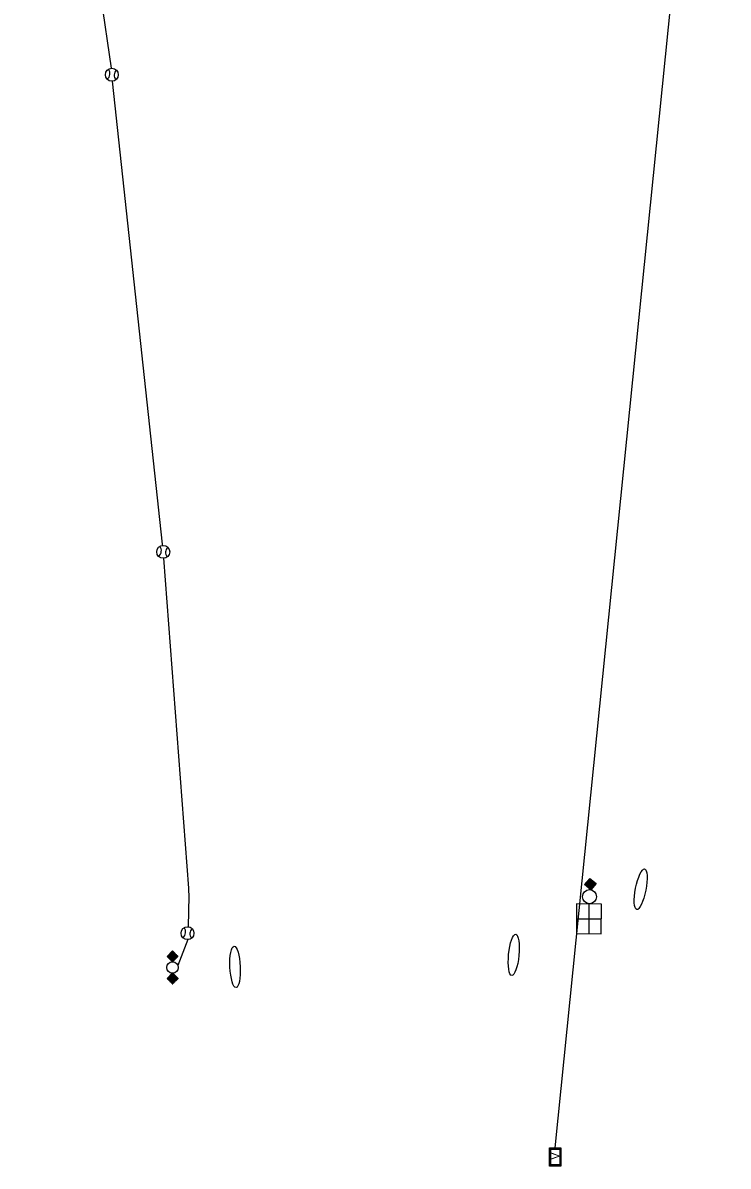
# Model space of a CAD drawing. Extents: x 584850 to 602551, y 145475 to 158627.
# Drawn here: x 594140 to 594577, y 153187 to 153895 of the extents above; entities that cross this region are included whole.
import ezdxf

# ---------------------------------------------------------------- set-up
doc = ezdxf.new("R2010")
doc.units = 0
doc.layers.add('B_MISC', color=7, linetype='Continuous')
doc.layers.add('E_RDWY', color=7, linetype='Continuous')

# ---------------------------------------------------------------- blocks, each defined once
blk = doc.blocks.new('PB24X42')
at = {"layer": 'E_RDWY'}
blk.add_circle((0, 0), 2, dxfattribs=at)
for centre, start, end in [((-2.59, 0.09), 308.3742, 47.6044), ((2.73, 0.07), 134.4184, 228.4474)]:
    blk.add_arc(centre, 2, start, end, dxfattribs=at)

msp = doc.modelspace()

# ---------------------------------------------------------------- linework, layer by layer
at = {"layer": 'B_MISC'}
for p, q in [((594469.73, 153198.28), (594576.82, 154259.36)), ((594194.8, 153867.11), (594139.91, 154245.19)), ((594226.44, 153572.23), (594195.44, 153859.06)), ((594242.7, 153359.11), (594227.19, 153563.53)), ((594242.51, 153335.26), (594242.84, 153354.47)), ((594242.02, 153327.29), (594235.82, 153311.35))]:
    msp.add_line(p, q, dxfattribs=at)
for centre, start, end in [((594176.91, 153565.37), 7.0373, 7.8773), ((594192.84, 153355.33), 359.01607, 4.33771)]:
    msp.add_arc(centre, 50, start, end, dxfattribs=at)
at = {"layer": 'E_RDWY'}
for p, q in [((594487.9, 153361.49), (594494.96, 153361.96)), ((594488.18, 153361.81), (594494.64, 153362.24)), ((594488.22, 153361.21), (594488.18, 153361.81)), ((594488.46, 153362.13), (594494.32, 153362.52)), ((594488.54, 153360.93), (594488.46, 153362.13)), ((594488.74, 153362.45), (594494, 153362.8)), ((594488.86, 153360.65), (594488.74, 153362.45)), ((594489.02, 153362.77), (594493.68, 153363.07)), ((594489.18, 153360.37), (594489.02, 153362.77)), ((594489.3, 153363.08), (594493.36, 153363.35)), ((594489.5, 153360.09), (594489.3, 153363.08)), ((594489.58, 153363.4), (594493.04, 153363.63)), ((594489.82, 153359.81), (594489.58, 153363.4)), ((594489.86, 153363.72), (594492.72, 153363.91)), ((594490.14, 153359.53), (594489.86, 153363.72)), ((594490.14, 153364.04), (594492.41, 153364.19)), ((594490.46, 153359.25), (594490.14, 153364.04)), ((594490.42, 153364.36), (594492.09, 153364.47)), ((594490.78, 153358.97), (594490.42, 153364.36)), ((594490.7, 153364.68), (594491.77, 153364.75)), ((594491.1, 153358.69), (594490.7, 153364.68)), ((594490.98, 153365), (594491.45, 153365.03)), ((594491.42, 153358.41), (594490.98, 153365)), ((594491.73, 153358.26), (594491.27, 153365.19)), ((594492.01, 153358.58), (594491.58, 153364.91)), ((594492.29, 153358.9), (594491.9, 153364.63)), ((594492.56, 153359.22), (594492.22, 153364.35)), ((594492.84, 153359.54), (594492.54, 153364.07)), ((594493.12, 153359.86), (594492.86, 153363.79)), ((594493.4, 153360.18), (594493.18, 153363.51)), ((594493.68, 153360.5), (594493.5, 153363.23)), ((594493.96, 153360.82), (594493.82, 153362.95)), ((594494.24, 153361.14), (594494.14, 153362.68)), ((594494.52, 153361.46), (594494.46, 153362.4)), ((594494.8, 153361.77), (594494.78, 153362.12)), ((594488.22, 153361.21), (594494.68, 153361.64)), ((594488.54, 153360.93), (594494.4, 153361.32)), ((594488.86, 153360.65), (594494.12, 153361)), ((594489.18, 153360.37), (594493.84, 153360.68)), ((594489.5, 153360.09), (594493.56, 153360.36)), ((594489.82, 153359.81), (594493.28, 153360.04)), ((594490.14, 153359.53), (594493, 153359.72)), ((594490.46, 153359.25), (594492.72, 153359.4)), ((594490.78, 153358.97), (594492.44, 153359.08)), ((594491.1, 153358.69), (594492.16, 153358.76)), ((594491.42, 153358.41), (594491.89, 153358.45)), ((594490.61, 153349.35), (594490.53, 153331)), ((594482.85, 153340.21), (594498.29, 153340.14)), ((594231.75, 153319.45), (594231.75, 153314.39)), ((594231.75, 153319.45), (594233.48, 153319.45)), ((594232.04, 153319.74), (594232.04, 153314.1)), ((594232.04, 153319.74), (594233.19, 153319.74)), ((594232.33, 153320.03), (594232.33, 153313.81)), ((594232.33, 153320.03), (594232.91, 153320.03)), ((594232.62, 153320.31), (594232.62, 153313.52)), ((594232.91, 153320.03), (594232.91, 153313.81)), ((594233.19, 153319.74), (594233.19, 153314.1)), ((594233.48, 153319.45), (594233.48, 153314.39)), ((594229.29, 153316.86), (594235.95, 153316.86)), ((594229.45, 153317.15), (594229.45, 153316.69)), ((594229.45, 153317.15), (594235.79, 153317.15)), ((594229.57, 153316.57), (594235.66, 153316.57)), ((594229.74, 153317.43), (594229.74, 153316.4)), ((594229.74, 153317.43), (594235.5, 153317.43)), ((594229.86, 153316.28), (594235.37, 153316.28)), ((594230.03, 153317.72), (594230.03, 153316.12)), ((594230.03, 153317.72), (594235.21, 153317.72)), ((594230.15, 153315.99), (594235.09, 153315.99)), ((594230.31, 153318.01), (594230.31, 153315.83)), ((594230.31, 153318.01), (594234.92, 153318.01)), ((594230.44, 153315.71), (594234.8, 153315.71)), ((594230.6, 153318.3), (594230.6, 153315.54)), ((594230.6, 153318.3), (594234.63, 153318.3)), ((594230.73, 153315.42), (594234.51, 153315.42)), ((594230.89, 153318.59), (594230.89, 153315.25)), ((594230.89, 153318.59), (594234.35, 153318.59)), ((594231.01, 153315.13), (594234.22, 153315.13)), ((594231.18, 153318.87), (594231.18, 153314.96)), ((594231.18, 153318.87), (594234.06, 153318.87)), ((594231.3, 153314.84), (594233.93, 153314.84)), ((594231.47, 153319.16), (594231.47, 153314.68)), ((594231.47, 153319.16), (594233.77, 153319.16)), ((594231.59, 153314.55), (594233.65, 153314.55)), ((594231.88, 153314.27), (594233.36, 153314.27)), ((594232.17, 153313.98), (594233.07, 153313.98)), ((594232.45, 153313.69), (594232.78, 153313.69)), ((594233.77, 153319.16), (594233.77, 153314.68)), ((594234.06, 153318.87), (594234.06, 153314.96)), ((594234.35, 153318.59), (594234.35, 153315.25)), ((594234.63, 153318.3), (594234.63, 153315.54)), ((594234.92, 153318.01), (594234.92, 153315.83)), ((594235.21, 153317.72), (594235.21, 153316.12)), ((594235.5, 153317.43), (594235.5, 153316.4)), ((594235.79, 153317.15), (594235.79, 153316.69)), ((594231.22, 153305.19), (594231.22, 153301.28)), ((594231.22, 153305.19), (594234.1, 153305.19)), ((594231.51, 153305.48), (594231.51, 153300.99)), ((594231.51, 153305.48), (594233.81, 153305.48)), ((594231.79, 153305.76), (594231.79, 153300.7)), ((594231.79, 153305.76), (594233.52, 153305.76)), ((594232.08, 153306.05), (594232.08, 153300.42)), ((594232.08, 153306.05), (594233.23, 153306.05)), ((594232.37, 153306.34), (594232.37, 153300.13)), ((594232.37, 153306.34), (594232.95, 153306.34)), ((594232.66, 153306.63), (594232.66, 153299.84)), ((594232.95, 153306.34), (594232.95, 153300.13)), ((594233.23, 153306.05), (594233.23, 153300.42)), ((594233.52, 153305.76), (594233.52, 153300.7)), ((594233.81, 153305.48), (594233.81, 153300.99)), ((594234.1, 153305.19), (594234.1, 153301.28)), ((594229.33, 153303.17), (594235.99, 153303.17)), ((594229.49, 153303.46), (594229.49, 153303.01)), ((594229.49, 153303.46), (594235.83, 153303.46)), ((594229.61, 153302.88), (594235.7, 153302.88)), ((594229.78, 153303.75), (594229.78, 153302.72)), ((594229.78, 153303.75), (594235.54, 153303.75)), ((594229.9, 153302.6), (594235.41, 153302.6)), ((594230.07, 153304.04), (594230.07, 153302.43)), ((594230.07, 153304.04), (594235.25, 153304.04)), ((594230.19, 153302.31), (594235.13, 153302.31)), ((594230.35, 153304.32), (594230.35, 153302.14)), ((594230.35, 153304.32), (594234.96, 153304.32)), ((594230.48, 153302.02), (594234.84, 153302.02)), ((594230.64, 153304.61), (594230.64, 153301.86)), ((594230.64, 153304.61), (594234.67, 153304.61)), ((594230.77, 153301.73), (594234.55, 153301.73)), ((594230.93, 153304.9), (594230.93, 153301.57)), ((594230.93, 153304.9), (594234.39, 153304.9)), ((594231.05, 153301.44), (594234.26, 153301.44)), ((594231.34, 153301.16), (594233.97, 153301.16)), ((594231.63, 153300.87), (594233.69, 153300.87)), ((594231.92, 153300.58), (594233.4, 153300.58)), ((594232.21, 153300.29), (594233.11, 153300.29)), ((594232.49, 153300), (594232.82, 153300)), ((594234.39, 153304.9), (594234.39, 153301.57)), ((594234.67, 153304.61), (594234.67, 153301.86)), ((594234.96, 153304.32), (594234.96, 153302.14)), ((594235.25, 153304.04), (594235.25, 153302.43)), ((594235.54, 153303.75), (594235.54, 153302.72)), ((594235.83, 153303.46), (594235.83, 153303.01))]:
    msp.add_line(p, q, dxfattribs=at)
for points in [[(594491.2, 153365.25), (594494.96, 153361.96), (594491.67, 153358.19), (594487.9, 153361.49)], [(594482.89, 153349.38), (594482.81, 153331.04), (594498.25, 153330.97), (594498.33, 153349.31)], [(594236.01, 153316.92), (594232.62, 153313.52), (594229.22, 153316.92), (594232.62, 153320.31)], [(594236.05, 153303.24), (594232.66, 153299.84), (594229.26, 153303.24), (594232.66, 153306.63)], [(594466.21, 153186.97), (594466.21, 153198.28), (594473.26, 153198.28), (594473.26, 153186.97)], [(594466.46, 153187.22), (594466.46, 153198.03), (594473.01, 153198.03), (594473.01, 153187.22)], [(594466.71, 153187.47), (594466.71, 153197.78), (594472.76, 153197.78), (594472.76, 153187.47)], [(594466.96, 153187.72), (594466.96, 153197.53), (594472.51, 153197.53), (594472.51, 153187.72)]]:
    msp.add_lwpolyline(points, close=True, dxfattribs=at)
for centre, radius in [((594490.94, 153353.89), 4.36), ((594232.59, 153310.01), 3.5)]:
    msp.add_circle(centre, radius, dxfattribs=at)
for centre, major_axis in [((594522.62, 153358.49), (-2.46, -12.58)), ((594444.02, 153317.81), (-1.24, -12.76)), ((594271.38, 153310.39), (0.58, -12.81))]:
    msp.add_ellipse(centre, major_axis=major_axis, ratio=0.249166, dxfattribs=at)

# ---------------------------------------------------------------- block references
at = {"layer": 'E_RDWY', "xscale": 2, "yscale": 2.0000000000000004, "rotation": -4.918194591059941}
for p in [(594195.03, 153863.08), (594226.86, 153567.51), (594241.91, 153331.28)]:
    msp.add_blockref('PB24X42', p, dxfattribs=at)

# ---------------------------------------------------------------- texts
at = {"layer": 'E_RDWY'}
msp.add_text('V', height=4.96, rotation=90, dxfattribs=at).set_placement((594472.21, 153191))

doc.saveas('drawing.dxf')
